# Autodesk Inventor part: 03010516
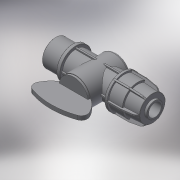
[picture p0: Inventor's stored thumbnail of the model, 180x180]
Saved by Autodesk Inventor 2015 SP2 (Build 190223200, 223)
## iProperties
Created: 2017-05
Part Number: 03010516
Material: Generic
Description: PLASSON 1/4 TURN VALVE MALE THREADED X COMPRESSION 16X1/2"
Document SubType Name: Modeling
Designer: KIM
Density: 1 g/cm^3
Appearance: Default
Author: KIM
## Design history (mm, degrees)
derived "03010.ipt"
feature "Solid1::03010.ipt"
tag "TaggingFeature1"
body "Solid1"
other parameters: "d0" = 98, "d1" = 15, "d3" = 20.955, "d4" = 12.59228, "d5" = 16, "d6" = 34, "d8" = 17, "d9" = 32.66667, "d10" = 2.45, "d11" = 30.6, "d12" = 27.2, "d13" = 25.5, "d14" = 2.45, "d15" = 20.955, "d16" = 25.146, "d17" = 18, "d19" = 0.245, "d25" = 1.47, "d26" = 0, "d27" = 4.9, "d29" = 360 deg, "d31" = 49, "d32" = 4.9, "d33" = 18.7, "d34" = 24.5, "d36" = 14.96, "d38" = 2.45, "d39" = 23.0505, "d40" = 1.47, "d41" = 0, "d43" = 360 deg, "d45" = 49, "d46" = 52, "d47" = 45, "d48" = 4, "d49" = 0, "d50" = 29, "d51" = 2, "d52" = 0, "d53" = 8, "d59" = 40 deg, "d60" = 25.5, "d62" = 3.02167, "L_" = 98, "A_" = 49, "E_" = 34, "l_" = 17, "l_1" = 15, "l_2" = 15, "R_" = 20.955, "d_" = 16, "d61" = 30.21667
